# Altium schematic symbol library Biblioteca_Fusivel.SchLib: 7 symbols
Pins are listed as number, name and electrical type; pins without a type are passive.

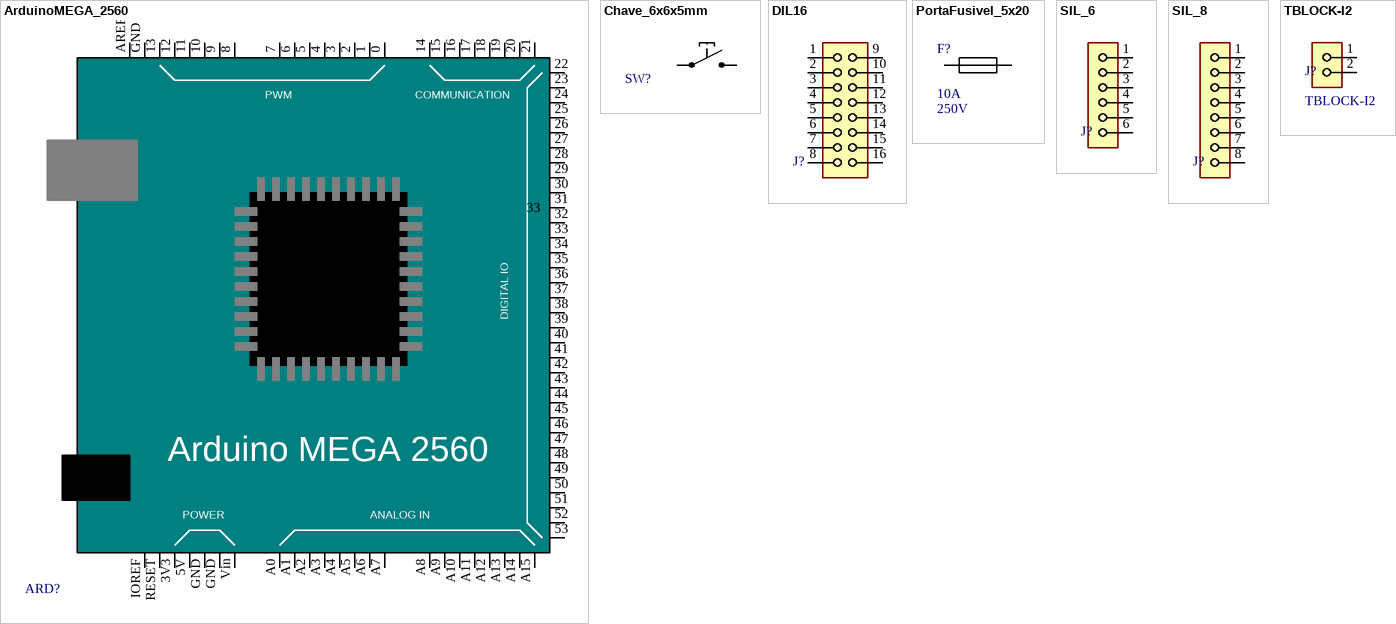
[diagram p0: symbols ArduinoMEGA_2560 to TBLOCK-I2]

## ArduinoMEGA_2560
designator ARD?  (value not drawn)
Arduino MEGA 2560
footprint ArduinoMEGA_2560
pins: 0 15, 1 14, 2 13, 3 12, 3V3 20, 4 11, 5 10, 5V 19, 6 9, 7 8, 8 7, 9 6, 10 5, 11 4, 12 3, 13 2, 14 16, 15 17, 16 18, 17 19, 18 20, 19 21, 20 22, 21 23, 22 24, 23 25, 24 26, 25 27, 26 28, 27 29, 28 30, 29 31, 30 32, 31 33, 32 24, 33 25, 34 26, 35 27, 36 28, 37 29, 38 30, 39 31, 40, 41 33, 42 24, 43 25, 44 26, 45 27, 46 28, 47 29, 48 30, 49 31, 50 32, 51 33, 52 34, 53 34, A0 15, A1 14, A2 13, A3 12, A4 11, A5 10, A6 9, A7 8, A8 7, A9 6, A10 5, A11 4, A12 3, A13 2, A14 1, A15 0, AREF 0, GND 1, GND 17, GND 18, IOREF 22, RESET 21, Vin 16

## Chave_6x6x5mm
designator SW?  (value not drawn)
Chave
footprint Chave_6x6x5mm
pins: 1, 3

## DIL16
designator J?  (value not drawn)
DIL16
footprint DIL16
pins: 1, 2, 3, 4, 5, 6, 7, 8, 9 1, 10 1, 11 1, 12 1, 13 1, 14 1, 15 1, 16 1

## PortaFusivel_5x20
designator F?, comment Corrente Máxima: 10A  Tensão Máxima: 250V  (hidden comment: Fusível de Vidro)
footprint PortaFusivel_5x20
pins: 1, 2

## SIL_6
designator J?  (value not drawn)
SIL_6
footprint SIL_6
pins: 1, 2, 3, 4, 5, 6

## SIL_8
designator J?  (value not drawn)
SIL 8 Connector
footprint SIL_8
pins: 1, 2, 3, 4, 5, 6, 7, 8

## TBLOCK-I2
designator J?
Borne KRE - 2 Vias
footprint TBLOCK-I2 (Borne KRE - 2 Vias)
pins: 1, 2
